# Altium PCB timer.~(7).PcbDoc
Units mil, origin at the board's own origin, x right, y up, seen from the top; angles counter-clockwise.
Board outline 1968.5 x 1968.5 mil, 2 copper layers (Top Layer, Bottom Layer); 44 components, 37 nets, 138 pads, 43 vias.
Unrouted connection lines stored in the file: 29.
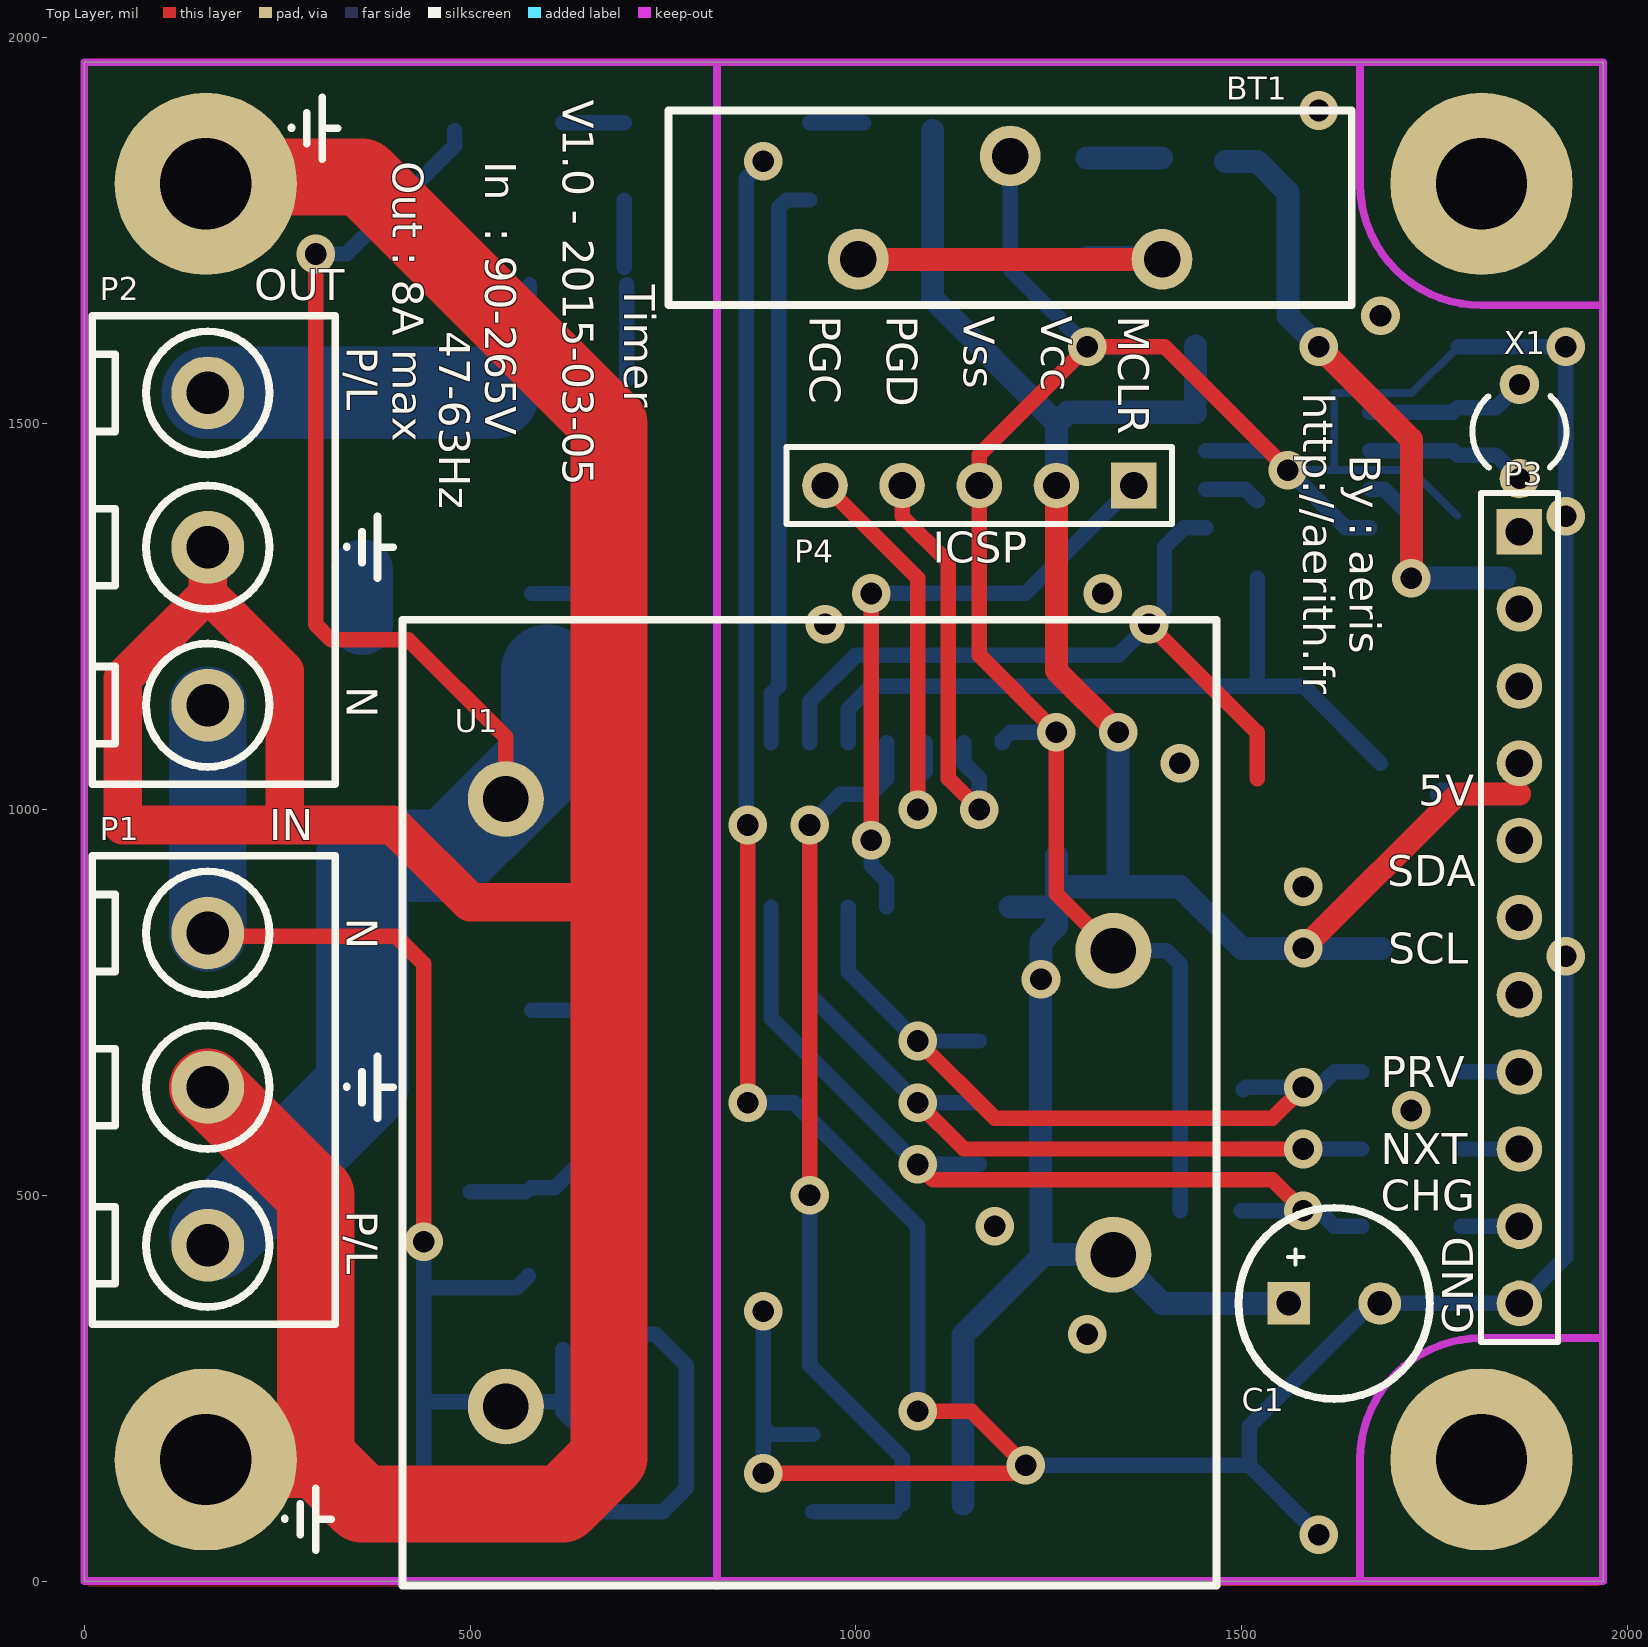
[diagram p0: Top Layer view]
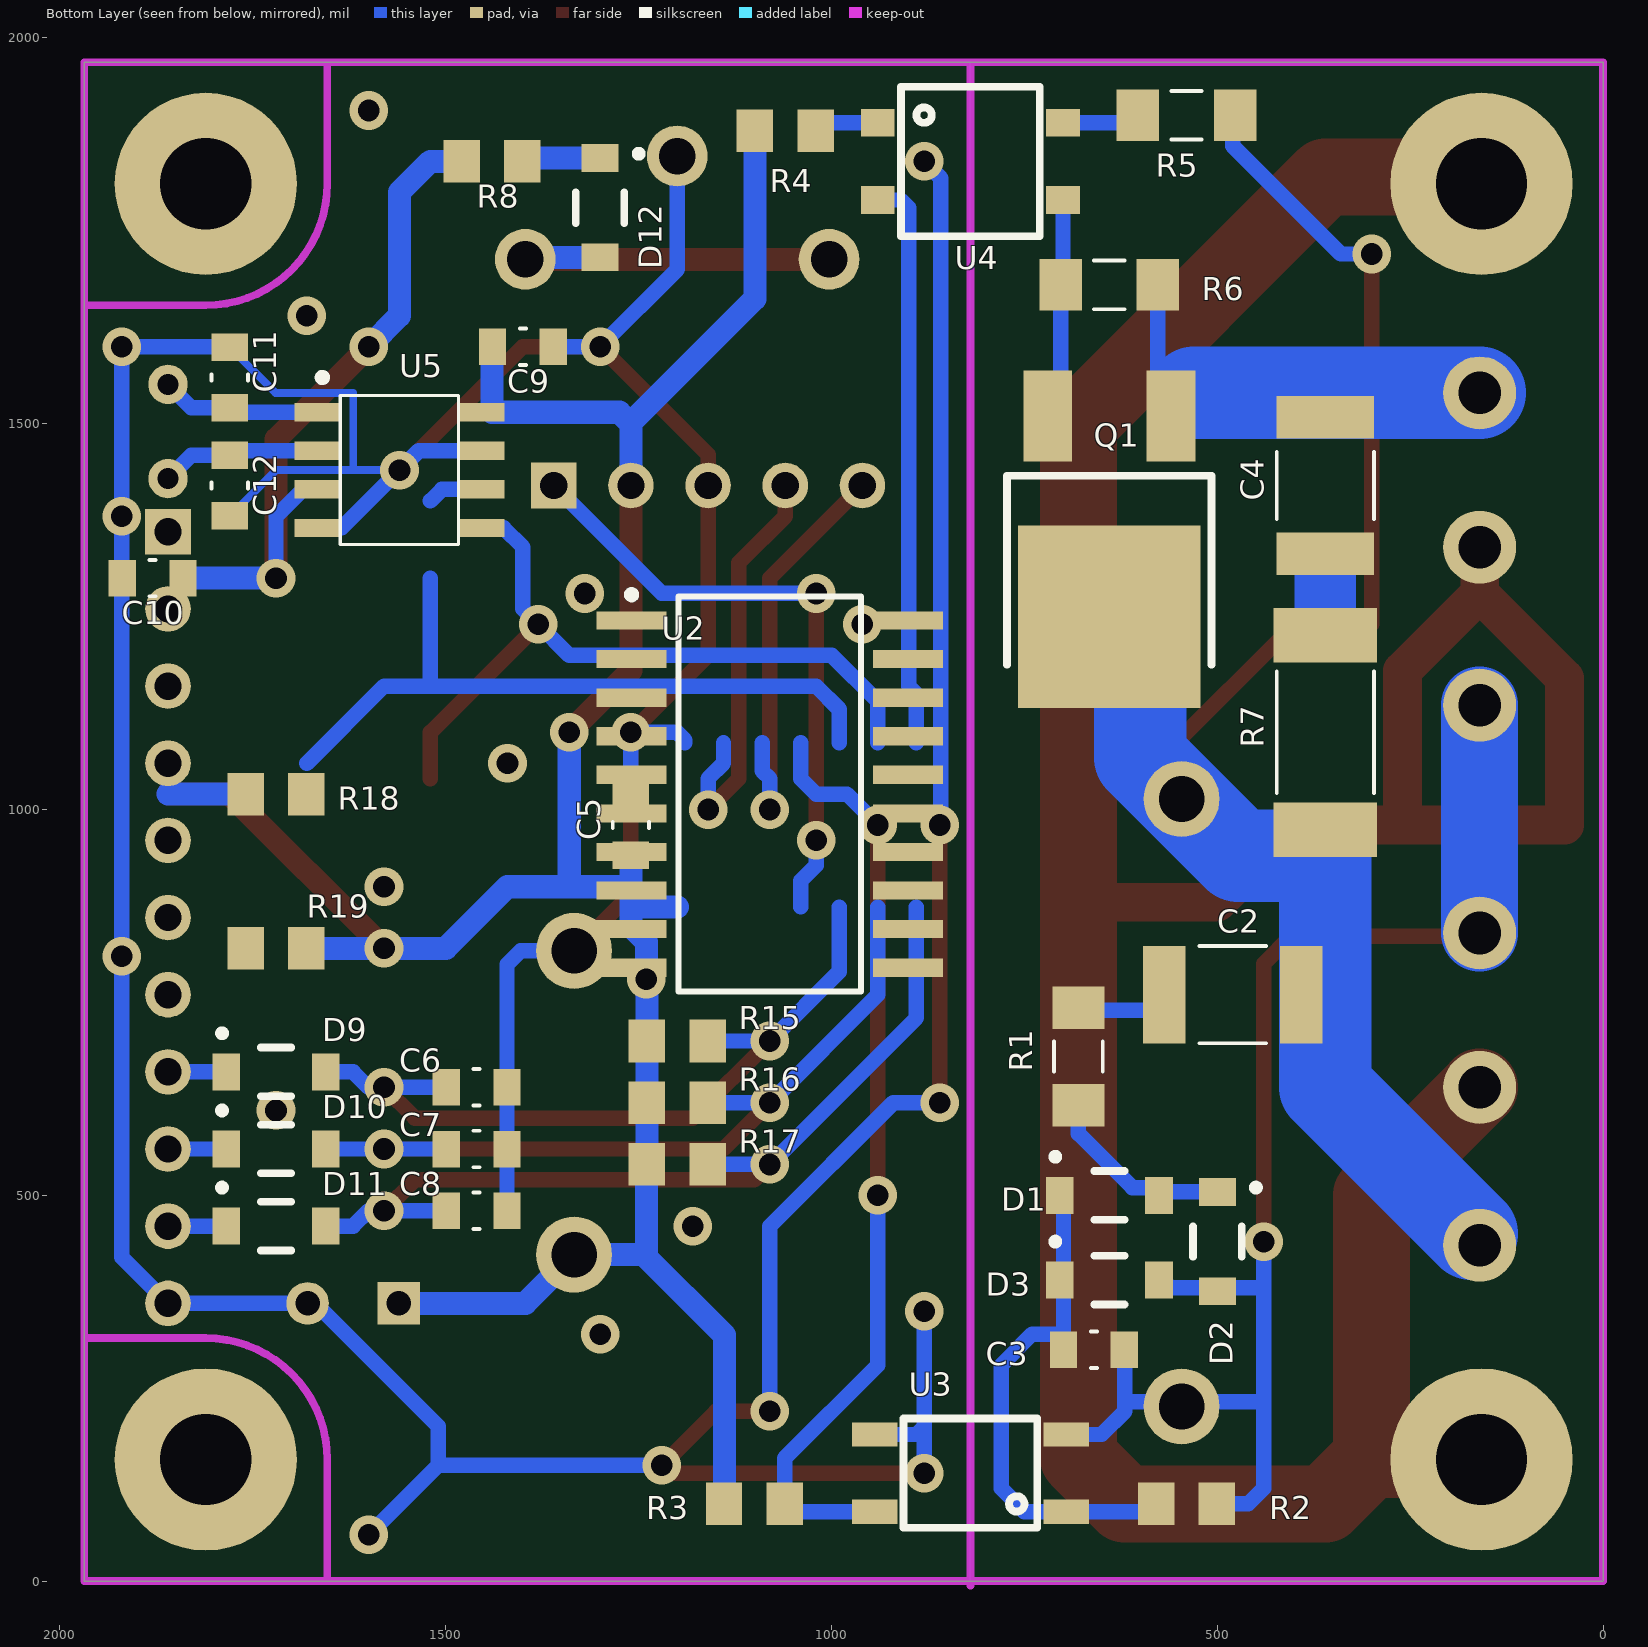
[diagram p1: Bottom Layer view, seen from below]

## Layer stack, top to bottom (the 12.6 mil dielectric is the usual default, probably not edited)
Top Layer: signal copper 1.4
Dielectric: core 12.6, FR-4, Dk 4.8
Bottom Layer: signal copper 1.4

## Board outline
0,0 1968.5,0 1968.5,1968.5 0,1968.5

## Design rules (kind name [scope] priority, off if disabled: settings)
Clearance RTC [InNetClass('RTC')] p1: gap=8
Clearance Earth [InNet('EARTH')] p2: gap=20
Clearance HT [InNetClass('HT') vs InNetClass('HT')] p3: gap=78.74
Clearance "plan masse" [All vs InNet('GND')] p4: gap=10
Clearance [All] p5: gap=20
HoleSize [All] p1: absolutevalues=TRUE maxlimit=196.85 minlimit=23.62 maxpercent=80.000 minpercent=20.000
PlaneConnect PlaneConnect_Via [isVia] p1: planeconnectstyle=Direct reliefexpansion=20 reliefentries=4 reliefconductorwidth=10 reliefairgap=10
PlaneConnect [All] p2: planeconnectstyle=Direct reliefexpansion=20 reliefentries=4 reliefconductorwidth=10 reliefairgap=10
PolygonConnect PolygonConnect_Via [IsVia] p1: connectstyle=Direct reliefconductorwidth=20 reliefentries=4 polygonreliefangle="90 Angle" airgapwidth=10
PolygonConnect [All] p2: connectstyle=Direct reliefconductorwidth=20 reliefentries=4 polygonreliefangle="90 Angle" airgapwidth=10
RoutingVias [All] p1: holewidth=39.37 width=78.74 viastyle="Through Hole" minholewidth=23.62 minwidth=31.5 maxholewidth=39.37 maxwidth=78.74
SilkToSolderMaskClearance SilkscreenOverComponentPads [IsPad] p1: minsilkscreentomaskgap=10 clearancetoexposedcopper=TRUE
SolderMaskExpansion [All] p1: expansion=4
Width overlay_width [(OnLayer('Top Overlay') OR OnLayer('Bottom Overlay'))] p1: maxlimit=10 minlimit=5 preferedwidth=10
Width [All] p2: maxlimit=150 minlimit=10 preferedwidth=20
25 further rules are at their usual default settings.

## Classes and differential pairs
net class RTC: NetC10_1 NetC11_1 NetC12_1
net class HT: N NetC4_1 NetC4_2 P

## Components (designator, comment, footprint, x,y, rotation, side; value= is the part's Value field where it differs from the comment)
BT1 "CR2032" BAT_2032 1200,1780 r0 top locked
C1 "470µ" CAP_6.3x2.5 1620,360 r0 top locked
C2 "10n 400V" C1812 480,760 r0 bottom
C3 "10n" C0805 660,300 r180 bottom
C4 "10n 400V" C1812 360,1420 r90 bottom
C5 "100n" C0805 1260,980 r270 bottom
C6 "100n" C0805 1460,640 r180 bottom
C7 "100n" C0805 1460,560 r180 bottom
C8 "100n" C0805 1460,480 r180 bottom
C9 "100n" C0805 1400,1600 r180 bottom
C10 "100p" C0805 1880,1300 r0 bottom
C11 "15p" C0805 1780,1560 r90 bottom
C12 "15p" C0805 1780,1420 r270 bottom
D1 "MBR0520LT" SOD-123 640,500 r0 bottom
D2 "MBR0520LT" SOD-123 500,440 r90 bottom
D3 "5V1" SOD-123 640,390 r0 bottom
D9 "MBR0520LT" SOD-123 1720,660 r0 bottom
D10 "MBR0520LT" SOD-123 1720,560 r0 bottom
D11 "MBR0520LT" SOD-123 1720,460 r0 bottom
D12 "MBR0520LT" SOD-123 1300,1780 r90 bottom
P1 "5.08x3" "BORNIER 5.08X3" 160,640 r270 top locked
P2 "5.08x3" "BORNIER 5.08X3" 160,1340 r270 top locked
P3 "2.54x11" HDR1X11 1860,1360 r270 top
P4 "2.54x5" HDR1X5 1360,1420 r180 top locked
Q1 "BT137S-600D" DPAK 640,1310 r0 bottom
R1 "10k" R1206 680,680 r90 bottom
R2 "100k" R0805 540,100 r180 bottom
R3 "10k" R0805 1100,100 r0 bottom
R4 "1k" R0805 1060,1880 r0 bottom
R5 "56" R1206 540,1900 r0 bottom
R6 "330" R1206 640,1680 r0 bottom
R7 "100 1W" R2512 360,1100 r90 bottom
R8 "1k" R0805 1440,1840 r0 bottom
R15 "10k" R0805 1200,700 r0 bottom
R16 "10k" R0805 1200,620 r0 bottom
R17 "10k" R0805 1200,540 r0 bottom
R18 "2k2" R0805 1720,1020 r180 bottom
R19 "2k2" R0805 1720,820 r0 bottom
U1 "AC-DC 5V 600mA" "AC-DC 3W" 940,620 r0 top locked
U2 "PIC16F1825" SOIC-20 1080,1020 r180 bottom
U3 "PC357N14J00F" OPTO_PC357N14J00F 820,140 r0 bottom
U4 "VOM160RT" OPTO_VOM160RT 820,1840 r180 bottom
U5 "MCP7940N" SOIC-8 1560,1440 r180 bottom
X1 "32.768kHz" R38 1860,1490 r0 top locked

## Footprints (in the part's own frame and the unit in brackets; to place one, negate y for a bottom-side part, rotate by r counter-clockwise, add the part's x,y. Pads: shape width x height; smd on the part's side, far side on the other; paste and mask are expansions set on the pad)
"AC-DC 3W" [mm]
  round 2.5 hole 1.5: 1(-10,10) 2(-10,-10) 3(10,-5) 4(10,5)
  silkscreen extent -13.4,-15.9 13.4,15.9, body extent -13.4,-15.9 13.4,15.9, height 19.5
BAT_2032 [mm] "Battery holder 2032"
  round 2 hole 1.2: +(-5,-1.7) +(5,-1.7) -(0,1.7)
  silkscreen extent -11.25,-3.2 11.25,3.2, body extent -11.25,-3.2 11.25,3.2, height 25
"BORNIER 5.08X3" [mm] "Bornier 5.08x3"
  round 2.4 hole 1.4: 1(-5.08,0) 2(0,0) 3(5.2,0)
  silkscreen extent -7.62,-3.8 7.8,4.2
C0805 [mm]
  rect 0.9x1.2 smd: 1(-1,0) 2(1,0)
  silkscreen extent -0.1,-0.6 0.1,0.6, body extent -1,-0.6 1,0.6, height 1.2
C1812 [mm]
  rect 1.4x3.2 smd: 1(-2.25,0) 2(2.25,0)
  silkscreen extent -1.1,-1.6 1.1,1.6, body extent -2.25,-1.6 2.25,1.6, height 3.2
CAP_6.3x2.5 [mm] "Capacitor throug hole dia=6.3mm, H=11mm, spacing=2.5mm"
  rect 1.4x1.4 hole 0.8: 1(-1.5,0)
  round 1.4 hole 0.8: 2(1.5,0)
  silkscreen extent -3.15,-3.15 3.15,3.15, body extent -3.12,-3.14 3.15,3.14, height 11
DPAK [mm] "DPAK"
  rect 1.6x3 smd: 1(-2.032,-5.08) 3(2.032,-5.08)
  rect 6x6 smd: 2(0,1.524)
  silkscreen extent -3.36,-3.11 3.36,3.11, body extent -3.36,-3.11 3.36,3.11, height 2.38
HDR1X5 [mm] "Connector; Header; 5 Position"
  rect 1.5x1.5 hole 0.9: 1(0,0)
  round 1.5 hole 0.9: 2(2.54,0) 3(5.08,0) 4(7.62,0) 5(10.16,0)
  silkscreen extent -1.27,-1.27 11.43,1.27
HDR1X11 [mm] "Connector; Header; 11 Position"
  rect 1.5x1.5 hole 0.9: 1(0,0)
  round 1.5 hole 0.9: 2(2.54,0) 3(5.08,0) 4(7.62,0) 5(10.16,0) 6(12.7,0) 7(15.24,0) 8(17.78,0) 9(20.32,0) 10(22.86,0) 11(25.4,0)
  silkscreen extent -1.27,-1.27 26.67,1.27
OPTO_PC357N14J00F [mm] "optocoupleur"
  rect 1.5x0.8 smd: 1(-3.15,1.27) 2(-3.15,-1.27) 3(3.15,-1.27) 4(3.15,1.27)
  silkscreen extent -2.2,-1.8 2.2,1.8, body extent -2.2,-1.8 2.2,1.8, height 2.6
OPTO_VOM160RT [mm] "Opto-triac"
  rect 1.11x0.91 smd: 1(-3.048,1.27) 2(-3.048,-1.27) 3(3.048,-1.27) 4(3.048,1.27)
  silkscreen extent -2.28,-2.46 2.28,2.46, body extent -2.28,-2.46 2.28,2.46, height 1.97
R38 [mm] "Crystal, Thru-Hole; 2 Leads; Body 3.1 x 8.2 mm (Dia.xH)"
  round 1.3 hole 0.7: 1(0,1.55) 2(0,-1.55)
  silkscreen extent -1.55,-1.19 1.55,1.17
R0805 [mm] "0.125W"
  rect 1.2x1.4 smd: 1(-1,0) 2(1,0)
  body extent -1,-0.63 1,0.63, height 1.2
R1206 [mm] "0.25W"
  rect 1.4x1.7 smd: 1(-1.6,0) 2(1.6,0)
  silkscreen extent -0.5,-0.8 0.5,0.8, body extent -1.6,-0.8 1.6,0.8, height 1.6
R2512 [mm] "1W"
  rect 1.8x3.4 smd: 1(-3.2,0) 2(3.2,0)
  silkscreen extent -2,-1.6 2,1.6, body extent -3.2,-1.6 3.2,1.6, height 5
SOD-123 [mm] "Diode"
  rect 0.91x1.22 smd: 1(-1.635,0) 2(1.635,0)
  silkscreen extent -0.5,-1.37 1.88,0.8, body extent -1.35,-0.8 1.35,0.8, height 1.17
SOIC-8 [mm] "8-Pin Plastic Narrow Body Small Outline Integrated Circuit 1.27 mm Pitch, IPC Medium Density"
  rect 1.5x0.6 smd: 1(-2.7,1.905) 2(-2.7,0.635) 3(-2.7,-0.635) 4(-2.7,-1.905) 5(2.7,-1.905) 6(2.7,-0.635) 7(2.7,0.635) 8(2.7,1.905)
  silkscreen extent -2.67,-2.45 1.95,3.17, body extent -1.95,-2.45 1.95,2.45, height 1.76
SOIC-20 [mm] "20-Pin Plastic Wide Body Small Outline Integrated Circuit 1.27 mm Pitch, IPC Medium Density"
  rect 2.3x0.6 smd: 1(-4.55,5.715) 2(-4.55,4.445) 3(-4.55,3.175) 4(-4.55,1.905) 5(-4.55,0.635) 6(-4.55,-0.635) 7(-4.55,-1.905) 8(-4.55,-3.175) 9(-4.55,-4.445) 10(-4.55,-5.715) 11(4.55,-5.715) 12(4.55,-4.445) 13(4.55,-3.175) 14(4.55,-1.905) 15(4.55,-0.635) 16(4.55,0.635) 17(4.55,1.905) 18(4.55,3.175) 19(4.55,4.445) 20(4.55,5.715)
  silkscreen extent -4.67,-6.5 3,6.69, body extent -3.75,-6.4 3.75,6.4, height 2.65

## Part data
BT1: library part Battery, "Multicell Battery"
C1: library part "Cap Pol1", "Polarized Capacitor (Radial)"
C2 C3 C4 C5 C6 C7 C8 C9 C10 C11 C12: library part Cap, "Capacitor"
D1 D2 D9 D10 D11 D12: library part "Diode 1N4001", "1 Amp General Purpose Rectifier"
D3: library part "D Zener", "Zener Diode"
P1 P2: library part "Header 3", "Header, 3-Pin"
P3: library part "Header 11", "Header, 11-Pin"
P4: library part "Header 5", "Header, 5-Pin"
Q1: library part Triac, "Silicon Bidirectional Triode Thyristor"
R1 R2 R3 R4 R5 R6 R7 R8 R15 R16 R17 R18 R19: library part Res2, "Resistor"
U1: library part AC-DC
U2: library part PIC16F1829
U3: library part Optoisolator1, "4-Pin Phototransistor Optocoupler"
U4: library part "Opto TRIAC", "Opto-Triac"
U5: library part "RTC- MCP7940N"
X1: library part XTAL, "Crystal Oscillator"

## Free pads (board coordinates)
  round 236.22 hole 118.11: 0(157.48,157.48) 0(157.48,1811.02) 0(1811.02,157.48) 0(1811.02,1811.02)

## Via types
v1: diameter 50, hole 28, Top Layer to Bottom Layer, 43 vias

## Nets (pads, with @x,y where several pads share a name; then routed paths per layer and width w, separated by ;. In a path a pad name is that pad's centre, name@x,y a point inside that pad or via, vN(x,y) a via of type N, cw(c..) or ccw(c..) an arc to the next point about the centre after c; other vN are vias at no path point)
BP_CHG: C8.1 D11.1 R17.1 U2.12 | length 1181.8
  Top Layer w20: v1(1080,540) 1100,520 1540,520 v1(1580,480)
  Bottom Layer w20: 890,873.7 890,730 v1(1080,540) R17.1@1160,540 ; C8.1 v1(1580,480) 1600,480 1620,460 D11.1
BP_NXT: C7.1 D10.1 R16.1 U2.2 | length 1072.8
  Top Layer w20: v1(1080,620) 1140,560 v1(1580,560)
  Bottom Layer w20: 940,873.7 940,760 v1(1080,620) R16.1@1160,620 ; C7.1 v1(1580,560) D10.1
BP_PRV: C6.1 D9.1 R15.1 U2.3 | length 1011.8
  Top Layer w20: v1(1080,700) 1180,600 1540,600 v1(1580,640)
  Bottom Layer w20: 990,873.7 990,790 v1(1080,700) R15.1@1160,700 ; C6.1@1502.38,636.99 1505.39,640 1600,640 1620,660 D9.1
EARTH: P1.2 P2.2 pad.0@157.48,157.48 pad.0@157.48,1811.02 | length 4671.4
  Top Layer w50: P2.2 160,1280 ; 680,880 500,880 400,980 260,980 ; 160,1280 50,1170 50,980 260,980 ; 160,1280 260,1180 260,980
  Top Layer w100: pad.0@157.48,1811.02 166.46,1820 360,1820 680,1500 680,880 680,160 620,100 360,100 302.52,157.48 157.48,157.48 300,157.48 300,500 P1.2
GND: BT1.- C1.2 C5.1 C6.2 C7.2 C8.2 C9.2 C10.2 C11.2 C12.2 P3.11 P4.3 U1.4 U2.20 U3.3 U5.4 U5.7 | length 7748.6
  Top Layer w20: v1(860,620) v1(860,980) ; v1(880,140) v1@1210,140 ; v1(1080,220) 1150,220 v1(1220,150) ; U1.4 1260,890.55 v1(1260,1100) 1160,1200 P4.3 1160,1460 v1(1300,1600) 1400,1600 v1(1560,1440)
  Bottom Layer w10: v1(1560,1440) 1620,1440 ; C12.2@1779.37,1380.63 1720,1440 1620,1440 ; C11.2 1720.63,1540 1620,1540 1620,1440
  Bottom Layer w20: v1(860,620) 920,620 1080,460 1080,230 v1@1070,220 ; v1(860,980) 858.19,981.81 858.19,1818.19 v1(880,1840) ; v1(880,140) 880,200 ; v1(880,350) 880,200 ; U3.3 890,190 880,200 ; 1190,1086.3 1190,1090 1200,1100 v1(1260,1100) C5.1 ; BT1.- 1200,1700 v1(1300,1600) C9.2 ; v1(1220,150) 1510,150 ; U1.4 1403.15,816.85 1420.63,799.37 C8.2 ; U5.7 1535,1465 v1(1560,1440) 1635,1365 U5.4 ; v1(1600,60) 1510,150 ; C11.2@1780.63,1600 v1(1920,1600) ; v1@1920,1580 1920,420 P3.11 1669.06,360 1510,200.94 1510,150
  other v1: 1300,320 1180,460 1720,610 1920,810 1580,900 1420,1060 960,1240 1320,1280 1920,1380 1680,1640 1600,1905.98
LCD_D4: P3.4 U2.7
LCD_D5: P3.5 U2.8
LCD_D6: P3.6 U2.9
LCD_D7: P3.7 U2.10
LCD_E: P3.3 U2.6
LCD_RS: P3.2 U2.5
MCLR: P4.1 U2.4 | length 812.4
  Top Layer w20: v1(1020,960) v1(1020,1280)
  Bottom Layer w20: v1(1020,960) 1020,927.47 1040,907.47 1040,873.7 ; v1@1020,1280.39 1220.39,1280.39 P4.1
N: C3.2 D2.1 D3.1 P1.1 P2.3 R2.2 U1.2 U3.2 | length 1834.8
  Top Layer w20: P1.1@164.25,835.75 404.25,835.75 440,800 v1(440,440)
  Bottom Layer w20: 440,380 560,380 D3.1@575.63,395.63 ; v1(440,440) 440,232.6 ; R2.2 460,100 440,120 440,232.6 ; 620,232.6 540,232.6 440,232.6 ; C3.2 620,300 620,220 650,190 U3.2
  Bottom Layer w50: U1.2@540,232.6 U1.2
  Bottom Layer w100: P1.1 P2.3
NetBT1_1: BT1.+ D12.1 | length 488
  Top Layer w30: BT1.+@1003.15,1713.07 BT1.+@1396.85,1713.07
  Bottom Layer w30: D12.1 BT1.+@1394.29,1715.63
NetC2_2: C2.2 R1.2 | length 100
  Bottom Layer w20: C2.2@580,740 R1.2@680,740
NetC3_1: C3.1 D1.2 D3.2 R2.1 U3.1 | length 639.6
  Bottom Layer w20: R2.1@580,90 U3.1 750,90 780,120 780,280 740,320 699.37,320 D1.2@699.37,490
NetC4_1: C4.1 R7.2 | length 70
  Bottom Layer w80: R7.2@360,1240 C4.1@360,1310
NetC4_2: C4.2 P2.1 Q1.1 R6.1 | length 523
  Bottom Layer w20: Q1.1@577.01,1527.01 R6.1
  Bottom Layer w120: P2.1 Q1.1@530,1540
NetC10_1: C10.1 R8.2 U5.3 | length 932.3
  Top Layer w30: v1(1600,1600) 1720,1480 v1(1720,1300)
  Bottom Layer w20: U5.3 1685,1415 1720,1380 v1(1720,1300)
  Bottom Layer w30: R8.2 1520,1840 1560,1800 1560,1640 v1(1600,1600) ; v1(1720,1300) C10.1
NetC11_1: C11.1 U5.1 X1.1 | length 200.7
  Bottom Layer w20: U5.1 C11.1@1774.37,1515 ; C11.1 1829.61,1520.63 X1.1
NetC12_1: C12.1 U5.2 X1.2 | length 200.7
  Bottom Layer w20: U5.2 C12.1@1774.37,1465 ; C12.1 1829.61,1459.37 X1.2
NetD1_1: D1.1 D2.2 R1.1 | length 220.3
  Bottom Layer w20: D2.2 D1.1@571.26,504.37 ; D1.1@580,510 610,510 680,580 R1.1@680,600
NetD12_2: D12.2 R8.1 | length 96.3
  Bottom Layer w30: D12.2 R8.1@1396.26,1844.37
NetQ1_3: Q1.3 R6.2 U4.3 | length 210
  Bottom Layer w20: R6.2@700,1702.99 U4.3 ; Q1.3@702.99,1557.01 R6.2
NetR4_1: R4.1 U4.1 | length 70
  Bottom Layer w20: U4.1 R4.1@1010,1890
NetR5_2: R5.2 U4.4 | length 80
  Bottom Layer w20: R5.2@620,1890 U4.4
P: C2.1 P1.3 Q1.2 R5.1 R7.1 U1.1 | length 2179
  Top Layer w20: v1(300,1720) 300,1240 320,1220 420,1220 546.3,1093.7 U1.1
  Bottom Layer w20: v1(300,1720) 340,1720 480,1860 R5.1@480,1880 ; Q1.2@580,1280 Q1.2@660,1280
  Bottom Layer w120: P1.3@170,450 360,640 360,940 472.6,940 U1.1 600,1067.4 Q1.2@600,1180
P_BP_CHG: D11.2 P3.10 | length 75.6
  Bottom Layer w20: D11.2 P3.10
P_BP_NXT: D10.2 P3.9 | length 75.6
  Bottom Layer w20: D10.2 P3.9
P_BP_PRV: D9.2 P3.8 | length 75.6
  Bottom Layer w20: D9.2 P3.8
PGC: P4.5 U2.18 | length 560.1
  Top Layer w20: P4.5 1080,1300 v1(1080,1000)
  Bottom Layer w20: v1(1080,1000) 1080,1040 1090,1050 1090,1086.3
PGD: P4.4 U2.19 | length 556
  Top Layer w20: P4.4 1060,1380 1120,1320 1120,1040 v1(1160,1000)
  Bottom Layer w20: 1140,1086.3 1140,1060 1160,1040 v1(1160,1000)
POWER: U2.14 U4.2 | length 742
  Bottom Layer w20: 890,1086.3 890,1150 900,1160 900,1780 910,1790 U4.2
SCL: R18.2 U2.11 U5.6 | length 1000.1
  Bottom Layer w20: 990,1086.3 990,1130 1020,1160 1520,1160 ; U5.6 1505,1415 1520,1400 ; 1520,1300 1520,1160 ; 1680,1060 1580,1160 1520,1160
SDA: R19.2 U2.13 U5.5 | length 965.5
  Top Layer w20: v1(1380,1240) 1520,1100 1520,1040
  Bottom Layer w20: 940,1086.3 940,1140 1000,1200 1340,1200 v1(1380,1240) 1400,1260 1400,1340 1425,1365 U5.5
SIGNAL: R3.1 U2.17 U3.4 | length 1207.7
  Top Layer w20: v1(940,500) v1(940,980)
  Bottom Layer w20: v1(940,500) 940,280 1060.63,159.37 R3.1 ; v1(940,980) 980,1020 1020,1020 1040,1040 1040,1086.3 ; U3.4 R3.1@1050.63,90
VCC: C1.1 C5.2 C9.1 P3.1 P4.2 R3.2 R4.2 R15.2 R16.2 R17.2 R18.1 R19.1 U1.3 U2.1 U5.8 | length 3538.1
  Top Layer w30: P4.2 1260,1180 v1(1340,1100) ; v1(1580,820) 1780,1020 1860,1020
  Bottom Layer w30: R4.2 1099.37,1661.89 1260,1501.26 1260,1500 ; R3.2@1138.74,100 1138.74,318.74 1243.15,423.15 U1.3 ; 1200,873.7 1253.7,873.7 ; v1@1239.37,780 R15.2 R16.2 1240,423.15 ; v1(1240,780) 1240,828.61 1260,848.61 1260,900 ; C5.2 1260,900 ; P4.2 1260,1500 ; U1.3@1337.8,419.06 1396.85,360 C1.1@1560,360 ; v1(1340,1100) 1340,900 ; U5.8@1440,1515 1275,1515 1260,1500 ; 1440,1528.7 C9.1@1440,1600.63 ; R19.1 v1(1580,820) 1500,820 1420,900 1340,900 ; R18.1 1860,1020 ; 1260,900 1340,900
pads on no net: U2.15 U2.16

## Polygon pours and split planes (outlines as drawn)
EARTH on Top Layer "Earth-Top" (solid, shelved, pour order 3): 0,0 5.98,-5.98 820,-5.98 820,1968.5 0,1968.5
GND on Top Layer "GND-Top" (solid, remove dead copper, shelved, pour order 7): 1968.5,0 1962.52,-5.98 820,-5.98 820,1968.5 1968.5,1968.5
GND on Bottom Layer "GND-Bottom" (solid, remove dead copper, shelved, pour order 5): 1968.5,0 820,0 820,1968.5 1968.5,1968.5

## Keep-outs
Top Layer:
  lines w10: 820,-5.98 820,1968.5 ; 1653.54,0 1653.54,157.48 cw(c1811.02,157.48) 1811.02,314.96 1968.5,314.96 ; 1653.54,1968.5 1653.54,1811.02 ccw(c1811.02,1811.02) 1811.02,1653.54 1968.5,1653.54
Bottom Layer:
  lines w10: 820,-5.98 820,1968.5 ; 1653.54,0 1653.54,157.48 cw(c1811.02,157.48) 1811.02,314.96 1968.5,314.96 ; 1653.54,1968.5 1653.54,1811.02 ccw(c1811.02,1811.02) 1811.02,1653.54 1968.5,1653.54
Keep-Out Layer:
  the board outline again, w10

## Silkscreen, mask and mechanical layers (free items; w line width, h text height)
Top Overlay:
  lines w10: 260,80 260,81 ; 268.5,1882.99 268.5,1883.99 ; 280,60 280,100 ; 288.5,1862.99 288.5,1902.99 ; 300,40 300,120 ; 300,80 320,80 ; 308.5,1842.99 308.5,1922.99 ; 308.5,1882.99 328.5,1882.99 ; 340,640 340,641 ; 340,1340 340,1341 ; 360,620 360,660 ; 360,1320 360,1360 ; 380,600 380,680 ; 380,640 400,640 ; 380,1300 380,1380 ; 380,1340 400,1340
  text "V1.0 - 2015-03-05" at 620,1920 h40 r270
  text "Out : 8A max" at 400,1840 h40 r270
  text "In  : 90-265V" at 520,1840 h40 r270
  text "Timer" at 700,1680 h40 r270
  text "OUT" at 220,1660 h40
  text "PGC" at 940,1640 h40 r270
  text "PGD" at 1040,1640 h40 r270
  text "Vss" at 1140,1640 h40 r270
  text "Vcc" at 1240,1640 h40 r270
  text "MCLR" at 1340,1640 h40 r270
  text "47-63Hz" at 460,1620 h40 r270
  text "P/L" at 340,1600 h40 r270
  text "http://aerith.fr" at 1580,1540 h40 r270
  text "By : aeris" at 1640,1460 h40 r270
  text "ICSP" at 1100,1320 h40
  text "N" at 340,1160 h40 r270
  text "5V" at 1728.65,1004.7 h40
  text "IN" at 240,960 h40
  text "SDA" at 1688.45,900.39 h40
  text "N" at 340,860 h40 r270
  text "SCL" at 1690,800 h40
  text "PRV" at 1680,640 h40
  text "NXT" at 1680,540 h40
  text "P/L" at 340,480 h40 r270
  text "CHG" at 1680,480 h40
  text "GND" at 1800,320 h40 r90

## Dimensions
0,0 to 0,1968.5 on Drill Guide
1968.5,1968.5 to 0,1968.5 on Drill Guide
